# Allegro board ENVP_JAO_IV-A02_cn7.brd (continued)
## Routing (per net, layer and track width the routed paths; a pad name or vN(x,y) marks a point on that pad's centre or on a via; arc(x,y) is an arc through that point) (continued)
GND_+3V3A_L: length 4.9
  TOP w0.254: v1(70.36,85.22) 70.23,85.48 U2.14 69.09,85.48 v1(68.83,85.22)
  TOP w0.508: v1(72.39,80.64) 72.53,80.63 C62.2 ; R47.2 C59.2 72.01,82.3 v1(72.39,82.68)
  vias: v1(67.82,86.23) v1(67.82,85.22) v1(68.33,85.72) v1(68.83,86.23) v1(69.47,80.64) v1(69.47,80.01) v1(70.1,80.64) v1(70.1,80.01) v1(70.36,84.58) v1(70.99,85.22) v1(70.99,84.58)
GND_EARTH: length 71.8
  TOP w0.508: 5,132.07 H2.1 ; H2.1 2.07,135 ; H2.1 5,137.93 ; H2.1 7.93,135
  L2-GND1 w0.508: H2.1 5,137.93 ; H2.1 2.07,135 ; H2.1 5,132.07 ; H2.1 7.93,135 ; CN1.1 6.63,117.98 ; CN1.1 5.54,116.89 ; CN1.1 5.54,119.08
  L6-IN2 w0.508: H2.1 7.93,135 ; H2.1 2.07,135 ; H2.1 5,137.93 ; H2.1 5,132.07 ; 5.54,116.89 CN1.1 ; CN1.1 5.54,119.08 ; CN1.1 6.63,117.98
  L7-GND2 w0.508: CN1.1 6.63,117.98 ; CN1.1 5.54,116.89 ; CN1.1 5.54,119.08 ; H2.1 7.93,135 ; H2.1 2.07,135 ; H2.1 5,137.93 ; H2.1 5,132.07
  BOTTOM w0.508: CN1.1 5.54,119.08 ; CN1.1 6.63,117.98 ; CN1.1 5.54,116.89 ; 2.07,135 H2.1 ; H2.1 5,137.93 ; H2.1 7.93,135 ; H2.1 5,132.07
  vias: v1(1.52,137.41) v1(1.52,135.64) v1(1.52,133.86) v1(1.52,132.33) v1(3.05,138.18) v1(5.46,119.63) v1(6.1,119.63) v1(6.73,119.63) v1(6.86,138.18) v1(7.37,119) v1(7.37,118.36) v1(7.37,117.47) v1(7.37,116.84) v1(7.62,132.33) v1(8.89,138.18) v1(9.14,136.14) v1(9.14,134.37) v1(9.14,132.59) v1(10.16,127.25) v1(10.16,126.49) v1(10.16,125.73) v1(10.16,124.97)
GND_IC:
  vias: v1(11.48,26.42) v1(11.46,25.1) v1(11.84,23.9) v1(13.28,25.27) v1(13.36,26.42) v1(13.36,23.9) v1(15.7,26.39) v1(15.67,25.22) v1(15.7,23.88) v1(18.31,25.15) v1(18.26,23.88) v1(18.36,26.39) v1(19.76,23.88) v1(20.52,25.17) v1(20.57,26.42)
V5V_EN: length 1.4
  TOP w0.102: R549.2 45.26,83.03 U108.4
V5V_OC#: length 2.8
  TOP w0.102: U108.3 47.57,81.71 47.29,81.99 R548.2 TP67.1
V5V_P1: length 18.4
  TOP w0.254: 50.19,78.08 U107.8
  TOP w0.508: R553.1 44.89,70.1 44.57,70.43 44.57,70.85 v1(44.58,70.87) ; 50.19,78.08 50.19,78.38 50.93,79.12 C420.1 50.47,79.81 50.28,79.62 C419.1 49.03,79.62 48.82,79.83 U108.1 47.96,79.17 v1(48.64,78.49)
  BOTTOM w0.508: v1(44.58,70.87) 44.89,70.87 46.25,72.22 46.25,76.12 48.62,78.49 v1(48.64,78.49)
VBUS1_DUT_Q: length 5.2
  BOTTOM w0.508: 27.09,69.02 27.63,69.02 28.19,68.45 28.19,66.04 ; v1(26.67,65.22) 25.23,65.22
  vias: v1(26.67,66.04) v1(26.67,64.14) v1(27.56,65.23) v1(28.19,64.14) v1(28.57,65.23) v1(29.34,65.02) v1(29.34,64.14) v1(29.34,63.25)
VBUS1_EN_R: length 8.2
  TOP w0.508: v1(24,67.12) 24.32,67.12 25.07,66.37 25.07,65.91 24.89,65.74 24,65.74
  BOTTOM w0.508: 27.09,67.12 25.24,67.12 25.23,67.12 v1(24,67.12) 23.88,67.24 TP62.1 24.13,68.45 R529.1
VBUS1_ENABLE_CONSUMER: length 14
  TOP w0.102: v1(31.88,62.74) 32.38,62.74 32.75,62.37 32.75,61.61 33.07,61.29 33.71,61.29 34.05,60.95 34.05,60.14
  L3-IN1 w0.102: v1(26.42,68.07) 27.43,68.07 31.88,63.63 v1(31.88,62.74)
  BOTTOM w0.102: 31.88,63.5 v1(31.88,62.74) ; v1(26.42,68.07) 26.04,68.45 R529.2
VBUS_C_CTRL_OR: length 7.9
  TOP w0.102: TP58.1 59.18,82.93 58.94,83.17 U104.1 58.94,83.81 58.55,84.2 57.02,84.2 56.64,83.82 56.64,82.8 56.26,82.42 55.75,82.42 55.18,81.85 U103.4
VBUS_C_CTRL_P1: length 27.7
  TOP w0.102: U107.12 47.65,76.05 v1(47.5,76.2) ; U100.2 55.37,84.71 54.99,84.33 v1(54.1,84.33) 54.1,82.93 53.9,82.73 R522.1 ; v1(49.02,84.33) 49.13,84.44 U102.1
  L3-IN1 w0.102: v1(54.1,84.33) 53.59,84.84 49.53,84.84 v1(49.02,84.33)
  BOTTOM w0.102: v1(54.1,84.33) 54.1,84.02 R521.2 54.94,83.19 55.5,83.19 56.01,82.68 56.01,79.06 54.16,77.22 48.51,77.22 v1(47.5,76.2)
VBUS_C_CTRL_P1_R: length 47.1
  TOP w0.102: v1(55.24,82.68) 55.37,82.8 U103.2 55.37,84.2 55.63,84.45 56.39,84.45 56.64,84.71 56.64,86.23 56.02,86.85 U100.4 ; v1(33.4,60.83) 33.4,60.14
  BOTTOM w0.102: v1(33.4,60.83) 33.4,59.84 33.6,59.64 34.34,59.64 34.52,59.82 35.48,59.82 36.04,60.38 36.63,60.38 39.17,62.92 39.17,68.63 41.3,70.76 42.14,70.76 45.09,73.71 45.09,75.56 48.52,78.99 51.05,78.99 52.2,77.85 54.36,77.85 55.5,78.99 TP55.1 55.5,82.42 v1(55.24,82.68)
VBUS_C_CTRL_P2: length 36
  TOP w0.102: v1(55.37,76.33) 55.37,76.07 54.84,75.54 U107.38 ; R546.2 R524.1 v1(50.42,84.33) 50.43,84.34 U102.3 ; U101.2 58.17,86.11 v1(57.78,86.49)
  BOTTOM w0.102: v1(55.37,76.33) 56.95,77.9 56.95,79.93 57.63,80.62 57.63,81.81 56.9,82.55 56.9,83.82 57.78,84.71 v1(57.78,86.49) 57.15,87.12 53.72,87.12 52.91,87.93 48.69,87.93 46.86,86.11 46.86,84.2 47.42,83.64 R524.1 v1(50.42,84.33)
VBUS_C_CTRL_P2_R: length 9.2
  TOP w0.102: R547.2 TP56.1 59.69,87.88 58.93,87.88 58.82,87.77 U101.4 58.82,87.11 59.31,86.61 59.31,84.71 59.05,84.45 56.72,84.45 U103.1
VBUS_DISCHARGE_P1: length 9.6
  TOP w0.102: U107.20 48.11,72.05 48.07,72.01 48.07,70.8 45.96,68.69 41.62,68.69 41.1,69.22
VBUS_MON_P1: length 7
  TOP w0.102: R555.2 R556.1 43.94,74.04 44.45,74.55 45.56,74.55 45.92,74.91 45.92,74.93 C425.1 47.62,75.18 47.99,75.54 U107.13
VBUS_P_CTRL_P1: length 23.9
  TOP w0.102: v1(43.94,75.18) 43.94,75.44 44.3,75.79 46.46,75.79 47.31,76.64 48.07,76.64 48.17,76.54 U107.11
  BOTTOM w0.102: v1(43.94,75.18) 43.87,75.11 43.87,72.82 42.04,70.99 41.08,70.99 39.12,69.02 37.91,69.02 37.59,68.71 37.59,62.15 36.4,60.96
VCC_DCIN: length 26.6
  TOP w0.254: C498.1 45.72,123.85 45.47,123.59 v1(45.47,123.19) ; 46.1,121.28 46.1,114.62 43.24,111.76 41.27,111.76 39.12,109.6 39.12,108.71 38.35,107.95 38.35,106.48 37.8,105.92 R696.2 R694.1
  TOP w0.508: 45.34,115.19 44.83,114.68 R845.1
  vias: v1(41.53,110.36) v1(41.53,109.73) v1(42.16,110.36) v1(42.16,109.73) v1(42.8,110.36) v1(42.8,109.73) v1(45.47,125.22) v1(45.47,124.59) v1(45.47,122.17) v1(46.74,125.22) v1(46.74,124.59) v1(46.74,123.19) v1(46.74,122.17) v1(50.04,137.67) v1(50.04,125.48) v1(50.04,124.21) v1(50.29,121.16) v1(50.29,120.4) v1(51.05,125.48) v1(51.05,124.21) v1(51.31,137.67) v1(51.56,121.16) v1(51.56,120.4) v1(52.07,125.48) v1(52.07,124.21) v1(52.83,137.67) v1(52.83,121.16) v1(52.83,120.4) v1(53.34,125.48) v1(53.34,124.21) v1(54.1,121.16) v1(54.1,120.4) v1(54.36,137.67) v1(54.36,125.48) v1(54.36,124.21) v1(55.37,125.48) v1(55.37,124.21) v1(55.37,123.19) v1(55.37,122.17) v1(55.37,121.16) v1(55.37,120.4) v1(56.13,137.67) v1(57.66,137.67)
VCC_DCIN+: length 30.8
  TOP w0.508: CN1.2 5.54,115.27 ; CN1.2 6.63,114.17 ; CN1.2 5.54,113.08 ; R803.1 37.8,107.62 v1(37.72,107.7) ; D31.2 v1(26.86,102.69) ; R700.1 v1(26.04,106.93) ; R425.2 v1(28.19,100.71)
  L2-GND1 w0.508: CN1.2 6.63,114.17 ; CN1.2 5.54,115.27 ; CN1.2 5.54,113.08
  L3-IN1 w0.508: 5.54,113.08 CN1.2 ; CN1.2 5.54,115.27 ; CN1.2 6.63,114.17
  L4-VCC1 w0.508: CN1.2 6.63,114.17 ; CN1.2 5.54,115.27 ; CN1.2 5.54,113.08
  L5-VCC2 w0.508: CN1.2 6.63,114.17 ; CN1.2 5.54,115.27 ; CN1.2 5.54,113.08
  L6-IN2 w0.508: 5.54,113.08 CN1.2 ; CN1.2 5.54,115.27 ; CN1.2 6.63,114.17
  L7-GND2 w0.508: 5.54,113.08 CN1.2 ; CN1.2 6.63,114.17 ; CN1.2 5.54,115.27
  BOTTOM w0.508: 5.54,113.08 CN1.2 ; CN1.2 6.63,114.17 ; CN1.2 5.54,115.27 ; v1(22.1,101.98) 21.51,101.98 R801.1 ; R112.1 v1(20.19,108.2)
  vias: v1(7.37,115.06) v1(7.37,113.28) v1(8.76,114.17) v1(9.4,112.27) v1(9.4,111.25) v1(9.4,110.24) v1(10.67,115.82) v1(10.67,114.55) v1(10.67,113.03) v1(10.92,127.51) v1(10.92,109.35) v1(10.92,108.71) v1(11.56,127.51) v1(12.19,113.03) v1(12.19,109.35) v1(12.19,108.71) v1(12.57,127.51) v1(13.08,117.86) v1(13.08,116.84) v1(13.21,127.51) v1(13.72,113.03) v1(13.72,109.35) v1(13.72,108.71) v1(14.35,127.51) v1(14.99,127.51) v1(15.24,117.86) v1(15.24,116.84) v1(15.24,115.57) v1(15.24,114.3) v1(15.24,113.03) v1(15.24,111.12) v1(15.24,109.86) v1(15.24,108.71) v1(16.13,127.51) v1(16.26,114.94) v1(16.26,114.17) v1(16.26,113.28) v1(16.26,111.89) v1(16.26,111) v1(16.26,110.11) v1(16.76,127.51) v1(16.89,116.59) v1(16.89,115.95) v1(16.89,109.47) v1(17.53,116.59) v1(17.53,115.95) v1(17.53,109.47) v1(17.65,127.51) v1(18.29,127.51) v1(19.81,137.79) v1(19.81,137.03) v1(19.81,135.76) v1(19.81,135.13) v1(19.81,133.99) v1(19.81,133.35) v1(19.81,132.21) v1(19.81,131.57) v1(19.81,130.3) v1(19.81,129.67) v1(19.81,128.52) v1(19.81,127.89)
VCC_DCIN-: length 35
  TOP w0.508: CN1.3 6.63,110.36 ; CN1.3 5.54,109.27 ; CN1.3 5.54,111.46 ; CN1.3 4.45,110.36
  L2-GND1 w0.508: CN1.3 6.63,110.36 ; CN1.3 4.45,110.36 ; CN1.3 5.54,111.46 ; CN1.3 5.54,109.27
  L3-IN1 w0.508: CN1.3 5.54,111.46 ; CN1.3 6.63,110.36 ; CN1.3 5.54,109.27 ; CN1.3 4.45,110.36
  L4-VCC1 w0.508: CN1.3 5.54,111.46 ; CN1.3 4.45,110.36 ; CN1.3 5.54,109.27 ; CN1.3 6.63,110.36
  L5-VCC2 w0.508: 5.54,109.27 CN1.3 ; CN1.3 6.63,110.36 ; CN1.3 5.54,111.46 ; CN1.3 4.45,110.36
  L6-IN2 w0.508: CN1.3 5.54,111.46 ; CN1.3 6.63,110.36 ; CN1.3 5.54,109.27 ; CN1.3 4.45,110.36
  L7-GND2 w0.508: 4.45,110.36 CN1.3 ; CN1.3 5.54,109.27 ; CN1.3 6.63,110.36 ; CN1.3 5.54,111.46
  BOTTOM w0.508: CN1.3 6.63,110.36 ; CN1.3 5.54,109.27 ; CN1.3 5.54,111.46 ; CN1.3 4.45,110.36
  vias: v1(2.54,129.54) v1(2.54,127) v1(2.54,124.46) v1(2.54,121.92) v1(2.54,119.38) v1(2.54,116.84) v1(2.54,114.3) v1(2.54,111.76) v1(2.54,109.22) v1(2.54,106.68) v1(2.54,104.14) v1(2.54,102.23) v1(4.19,110.36) v1(5.08,121.92) v1(5.08,106.68) v1(5.08,104.14) v1(5.08,102.23) v1(5.59,126.49) v1(5.59,125.22) v1(5.59,123.95) v1(5.84,108.71) v1(6.1,129.79) v1(6.1,129.03) v1(6.86,129.79) v1(6.86,129.03) v1(7.49,110.36) v1(7.62,121.92) v1(7.62,106.68) v1(7.62,104.14) v1(7.62,102.23) v1(8.38,126.49) v1(8.38,125.22) v1(8.38,123.95) v1(10.16,102.23) v1(10.67,104.65) v1(10.67,103.63) v1(11.43,105.66) v1(11.43,102.87) v1(12.7,102.23) v1(12.95,105.66) v1(12.95,102.87) v1(14.22,105.66) v1(14.22,102.87) v1(14.73,102.23) v1(14.99,104.65) v1(14.99,103.63) v1(15.62,102.87) v1(16,105.16) v1(16,104.39) v1(16,103.63) v1(16.38,102.23) v1(16.76,105.92) v1(17.14,102.23) v1(17.53,105.92) v1(17.91,102.23) v1(18.29,105.92)
VCC_DCIN_EN: length 6.4
  BOTTOM w0.254: Q66.1 47.48,120.13 47.8,120.45 R702.1 C504.2 R703.1 45.59,119.05 Q67.3
VCC_DCIN_EN_MID: length 1.6
  BOTTOM w0.254: R699.2 47.55,116.73 Q66.3
VCC_DCIN_EN_N: length 17.6
  TOP w0.508: v1(49.02,114.3) 48.1,114.3 47.89,114.08 C622.2
  L3-IN1 w0.508: v1(54.36,114.55) 53.34,115.57 49.78,115.57 49.02,114.81 v1(49.02,114.3)
  BOTTOM w0.508: C502.2 48.79,114.07 v1(49.02,114.3) ; C502.2 47.88,114.94 48.46,115.52 R699.1 49.91,115.95 50.42,116.46 Q62.4 ; C502.2 46.43,114.07 R695.2 ; Q63.4 54.1,114.3 v1(54.36,114.55)
VCC_DCIN_PG: length 3
  TOP w0.203: U124.14 35.21,107.6 35.43,107.82 TP101.1 36.7,107.11 R803.2
VCC_DCIN_Q:
  vias: v1(46.1,112.39) v1(46.1,111.76) v1(46.74,112.39) v1(49.02,113.16) v1(49.02,112.39) v1(49.02,111.76) v1(49.66,113.79) v1(49.66,113.16) v1(49.66,112.39) v1(49.66,111.76) v1(50.04,114.43) v1(50.67,114.43) v1(50.8,111.76) v1(51.44,111.76) v1(51.56,114.43) v1(52.32,111.76) v1(52.45,114.43) v1(52.96,111.76) v1(53.09,114.43)
VCC_SRC: length 47.8
  TOP w0.508: C44.1 75.34,94.11 ; C44.1 74.45,93.22 ; C44.1 76.23,93.22 ; C44.1 75.34,92.33 ; C45.1 75.34,102.62 ; C45.1 75.34,100.84 ; C45.1 76.23,101.73 ; C45.1 74.45,101.73 ; R115.1 84.38,92.2 v1(83.82,92.2) ; v1(73.79,104.44) R477.1 72.47,104.44 72.39,104.52 D1.2 ; R32.1 v1(68.58,80.64) ; v1(73.91,88.9) 74.17,88.65 R30.1
  L4-VCC1 w0.508: 74.45,101.73 C45.1 ; C45.1 75.34,102.62 ; C45.1 76.23,101.73 ; C45.1 75.34,100.84 ; 74.45,93.22 C44.1 ; C44.1 75.34,94.11 ; C44.1 76.23,93.22 ; C44.1 75.34,92.33
  L6-IN2 w0.508: C44.1 75.34,90.32 v1(73.91,88.9)
  BOTTOM w0.508: 75.34,100.84 C45.1 ; C45.1 76.23,101.73 ; C45.1 75.34,102.62 ; C45.1 74.45,101.73 ; C44.1 75.34,94.11 ; C44.1 74.45,93.22 ; C44.1 75.34,92.33 ; C44.1 76.23,93.22 ; v1(73.91,88.9) 73.91,79.25 73.15,78.49 69.09,78.49 68.58,78.99 v1(68.58,80.64)
  vias: v1(59.05,115.19) v1(59.05,114.55) v1(59.94,115.19) v1(59.94,114.55) v1(60.83,115.19) v1(60.83,114.55) v1(61.98,126.11) v1(61.98,125.48) v1(61.98,124.84) v1(61.98,124.21) v1(61.98,121.92) v1(61.98,121.28) v1(62.61,121.92) v1(62.61,121.28) v1(62.61,117.98) v1(62.61,117.35) v1(62.87,115.32) v1(63.25,117.98) v1(63.25,117.35) v1(63.5,115.32) v1(63.63,121.92) v1(63.63,121.28) v1(63.88,117.98) v1(63.88,117.35) v1(64.26,121.92) v1(64.26,121.28) v1(65.02,115.32) v1(65.66,115.32) v1(67.18,117.98) v1(67.18,117.35) v1(67.44,115.32) v1(67.82,117.98) v1(67.82,117.35) v1(67.82,95) v1(68.07,115.32) v1(68.45,101.98) v1(68.45,101.09) v1(68.45,95) v1(69.34,102.87) v1(69.34,101.98) v1(69.34,101.09) v1(69.34,95) v1(69.98,95) v1(70.36,101.98) v1(70.36,101.09) v1(70.87,95) v1(71.12,102.87) v1(71.5,95) v1(71.63,101.98) v1(71.63,101.09) v1(72.39,95) v1(72.39,94.36) v1(72.9,102.87) v1(73.15,101.09) v1(73.15,100.08) v1(73.15,99.06) v1(73.15,98.04) v1(73.15,97.03) v1(73.15,96.01) v1(73.79,94.74) v1(73.91,101.47) v1(73.91,93.22) v1(74.36,102.87) v1(74.68,97.54) v1(74.68,95.5) v1(75.31,100.08) v1(75.31,98.81) v1(75.31,94.61) v1(75.82,86.11) v1(75.82,85.47) v1(75.82,84.84) v1(75.82,82.8) v1(76.2,97.54) v1(76.2,95.5) v1(76.45,86.11) v1(76.45,85.47) v1(76.45,84.84) v1(76.45,82.8) v1(76.58,100.08) v1(76.58,98.81) v1(76.71,101.47) v1(76.71,93.22) v1(77.09,86.11) v1(77.09,85.47) v1(77.09,84.84) v1(77.09,82.8) v1(77.47,84.07) v1(77.47,83.44) v1(77.72,86.11) v1(77.72,85.47) v1(77.72,84.84) v1(78.11,84.07) v1(78.11,83.44) v1(83.19,92.84) v1(83.19,92.2) v1(83.82,92.84) v1(86.11,92.71) v1(86.11,92.08) v1(86.74,92.96) v1(86.74,92.33) v1(151.51,101.09) v1(151.51,95.12) v1(151.76,104.78) v1(152.15,92.13) v1(152.4,101.09) v1(152.4,95.12) v1(152.63,99.59) v1(152.65,103.63) v1(152.9,97.79) v1(153.29,101.09) v1(153.31,95.12) v1(153.42,103.63) v1(153.54,99.57) v1(153.55,97.53) v1(153.61,98.17) v1(153.8,93.85) v1(154.69,104.78) v1(154.69,104.14) v1(155.32,104.78) v1(155.32,104.14) v1(155.96,104.78) v1(155.96,104.14)
VCC_SRC_FET: length 51.8
  TOP w0.381: C380.1 R705.1 90.55,87.76 v1(89.92,87.12)
  BOTTOM w0.381: 59.05,106.17 61.59,106.17 62.48,105.28 66.29,105.28 67.82,103.76 80.01,103.76 80.53,103.24 80.53,88.63 81.14,88.02 89.01,88.02 v1(89.92,87.12)
  BOTTOM w0.508: 56.9,104.27 57.53,103.63 C126.1
  vias: v1(21.34,56.64) v1(21.34,56.01) v1(21.34,54.74) v1(21.34,54.1) v1(21.97,56.64) v1(21.97,56.01) v1(21.97,54.74) v1(21.97,54.1) v1(23.75,56.64) v1(23.75,56.01) v1(23.75,54.74) v1(23.75,54.1) v1(24.38,56.64) v1(24.38,56.01) v1(24.38,54.74) v1(24.38,54.1) v1(26.04,59.44) v1(26.04,58.8) v1(26.29,56.64) v1(26.29,56.01) v1(26.29,54.74) v1(26.29,54.1) v1(26.67,59.44) v1(26.67,58.8) v1(26.92,56.64) v1(26.92,56.01) v1(26.92,54.74) v1(26.92,54.1) v1(28.19,59.44) v1(28.19,58.8) v1(28.83,59.44) v1(28.83,58.8) v1(31.11,58.67) v1(31.11,58.04) v1(31.11,56.52) v1(31.11,55.88) v1(31.11,54.61) v1(31.11,53.98) v1(31.75,58.67) v1(31.75,58.04) v1(31.75,56.52) v1(31.75,55.88) v1(31.75,54.61) v1(31.75,53.98) v1(32.77,58.67) v1(32.77,58.04) v1(32.77,56.52) v1(32.77,55.88) v1(32.77,54.61) v1(32.77,53.98) v1(33.91,58.67) v1(33.91,58.04) v1(34.54,58.67) v1(34.54,58.04) v1(35.18,58.67) v1(35.18,58.04) v1(36.32,58.67) v1(36.32,58.04) v1(36.32,57.4) v1(36.96,58.67) v1(36.96,58.04) v1(36.96,57.4) v1(52.07,106.17) v1(52.07,105.54) v1(53.09,106.17) v1(53.09,105.54) v1(53.09,104.52) v1(53.09,103.89) v1(54.1,106.17) v1(54.1,105.54) v1(54.1,104.52) v1(54.1,103.89) v1(54.86,106.17) v1(54.86,105.54) v1(55.63,106.17) v1(55.63,105.54) v1(56.39,106.17) v1(56.39,105.54) v1(57.4,106.17) v1(57.4,105.54) v1(58.17,105.54)
VCCD_1V8: length 2.4
  TOP w0.254: C418.2 56.77,73.05 U107.33
VDD1: length 2.7
  BOTTOM w0.254: 28.92,95.96 28.92,96.84 29.87,97.79 C457.1
VDD12V_DISCHARGE: length 63.9
  TOP w0.102: Q16.1 78.67,136.84 80.64,138.81 86.87,138.81 v1(87.86,137.82)
  BOTTOM w0.102: v1(87.86,137.82) 87.86,131.22 88.39,130.68 88.39,125.86 87.95,125.41 87.95,116.78 85.72,114.55 84.45,114.55 77.6,107.7 73.03,107.7 71.37,109.35 71.37,110.11 70.99,110.49 69.72,110.49 69.34,110.11 69.34,109.73 68.83,109.22 67.06,109.22 66.67,108.84 66.67,108.13 R109.2 67.71,107.1 D4.3
VDD_1V2:
  vias: v1(136.06,30.08) v1(138.22,36.77) v1(139.19,36.77) v1(140.91,36.64) v1(145.67,34.16) v1(145.92,32.38)
VDD_1V8: length 29.2
  TOP w0.254: 70.87,110.67 Q14.2
  TOP w0.305: 15.11,50.89 15.11,50.5 15.75,49.86
  TOP w0.381: 15.06,54.1 v1(16.13,54.1) ; v1(14.99,49.4) 14.53,48.95 14.35,48.95 ; v1(16.38,49.86) 15.75,49.86
  TOP w0.508: 70.87,110.67 70.74,110.54 v1(70.74,109.98) 70.74,109.27 R105.1
  BOTTOM w0.254: 37.97,84.71 37.97,84.33 37.63,83.99 37.01,83.99 ; 37.26,79.5 37.26,78.82 37.72,78.36 37.72,77.34 37.5,77.13 37.01,77.13
  BOTTOM w0.381: 41.61,84.84 v1(42.42,84.84) ; 41.61,82.55 v1(42.42,82.55) ; 41.61,78.61 v1(42.29,78.61) ; 41.61,81.41 42.16,81.41 v1(42.29,81.28) ; 41.61,77.34 42.04,77.34 v1(42.29,77.6) ; 41.61,83.69 v1(42.42,83.69) ; 41.61,75.95 41.61,74.37 41,73.76 v1(41,73.41)
  BOTTOM w0.508: 96.44,78.87 95.49,77.91 95.49,76.82 95.15,76.48 v1(95.15,76.45) ; 37.26,79.5 36.14,79.5 v1(36.14,78.74) ; 37.97,84.71 37.97,85.52 37.59,85.9 37.08,85.39 v1(37.08,85.22) ; 36.32,86.82 36.5,86.82 v1(36.96,86.36) ; 184.48,29.72 v1(184.48,33.02)
  vias: v1(26.54,44.4) v1(29.34,44.7) v1(30.61,29.97) v1(32.89,29.97) v1(37.34,29.97) v1(41.88,69.47) v1(42.57,69.47) v1(56.64,28.83) v1(64.52,79.76) v1(65.15,79.76) v1(65.15,79.12) v1(65.79,79.76) v1(65.79,79.12) v1(65.79,78.49) v1(88.2,73.24) v1(88.33,73.88) v1(88.86,73.24) v1(88.99,73.88) v1(95.89,81.79) v1(97.54,77.09) v1(107.06,78.49) v1(108.2,80.77) v1(110.36,84.26) v1(112.46,84.26) v1(113.16,46.74) v1(113.79,84.07) v1(114.53,46.71) v1(115.32,51.82) v1(119.89,79.76) v1(120.52,88.28) v1(120.5,87.6) v1(121.15,87.59) v1(121.17,88.27) v1(126.36,77.72) v1(137.97,70.43) v1(138.05,62.1) v1(138.18,63.75) v1(139.57,72.97) v1(140.49,58.75) v1(140.77,76.12) v1(142.21,77.57) v1(143.64,74.68) v1(150.81,63.06) v1(153.54,54.61) v1(154.81,56.52) v1(157.23,64.01) v1(163.58,45.59) v1(164.97,53.92) v1(165.23,49.53) v1(169.54,74.04) v1(171.2,61.72) v1(171.3,31.75) v1(172.47,31.75) v1(173.61,62.48) v1(173.61,61.21) v1(173.61,59.94) v1(173.61,57.4) v1(173.74,56.13) v1(175.84,51.61) v1(175.97,49.83) v1(176.73,38.18) v1(177.42,102.49) v1(177.62,28.52) v4(163.64,94.55)
VDD_1V8_PG: length 1.6
  TOP w0.102: v1(81.28,80.77) 81.14,80.91 U3.5
  BOTTOM w0.102: v1(81.28,80.77) 81.36,80.85 R72.2
VDD_3V3: length 109
  TOP w0.254: 92.22,114.74 92.22,113.3 91.95,113.03 v1(91.57,113.03) 91.57,113.41 91.72,113.56 91.72,114.74
  TOP w0.508: v1(17.14,58.93) 17.73,58.93 18.8,60.12 ; v1(85.6,64.39) 86.36,63.63 86.36,62.23 87.76,60.83 v1(87.76,60.2) 87.76,60.07 86.79,59.11 83.74,59.11 80.26,55.63 v1(80.26,53.98) ; 18.8,64.34 v1(18.8,65.02) ; v1(42.93,77.6) 42.93,77.19 42.19,76.45 41.53,76.45 40.77,75.69 34.92,75.69 v1(33.53,74.3) ; R550.1 v1(44.58,73.91) ; v1(91.57,113.03) v1(90.93,113.03)
  L3-IN1 w0.508: v1(14.22,64.39) 14.86,65.02 v1(18.8,65.02) 24.38,70.61 v1(26.04,70.61) 28.45,73.03 v1(30.86,73.03) 32.26,73.03 v1(33.53,74.3) ; v1(180.8,41.27) 180.8,35.61 183.9,32.51 183.9,24.64 v1(184.28,24.26)
  L6-IN2 w0.508: v1(35.78,88.32) 33.57,86.11 v1(31.88,86.11) 31.11,86.87 27.94,86.87 27.18,86.11 v1(26.04,86.11)
  BOTTOM w0.381: 32.72,74.3 v1(33.53,74.3) ; v1(87.76,60.2) 88.21,59.74 88.39,59.74 ; 30.86,72.34 v1(30.86,73.03) ; v1(88.77,105.79) 88.52,105.79 88.34,105.97 R649.1 ; 183.59,24.26 v1(184.28,24.26) ; v1(85.6,64.39) R502.1
  BOTTOM w0.508: v1(26.04,70.61) 26.04,70.99 26.16,71.12 R674.2 R671.2 ; v1(14.22,64.39) 13.84,64.01 13.84,59.44 14.35,58.93 v1(17.14,58.93) ; R617.2 R620.2 v1(26.04,86.11) ; R73.1 78.54,82.09 v1(78.74,82.3) ; 30.73,86.79 31.88,86.79 v1(31.88,86.11) ; 90.63,113.97 C467.1
  vias: v1(35.76,89.62) v1(35.78,88.95) v1(36.4,89.62) v1(36.41,88.95) v1(36.41,88.32) v1(37.29,89.6) v1(37.29,88.94) v1(37.29,88.3) v1(37.92,89.6) v1(37.92,88.94) v1(37.92,88.3) v1(38.73,91.88) v1(38.73,91.25) v1(38.73,90.36) v1(38.73,89.73) v1(38.73,89.03) v1(38.73,88.39) v1(39.37,91.88) v1(39.37,91.25) v1(39.37,90.36) v1(39.37,89.73) v1(39.37,89.03) v1(39.37,88.39) v1(51.56,37.97) v1(52.2,37.97) v1(52.83,37.97) v1(60.58,35.43) v1(60.71,36.58) v1(61.59,30.61) v1(73.66,32.51) v1(74.3,32.51) v1(77.47,30.61) v1(93.47,110.49) v1(94.11,110.49) v1(94.22,113.05) v1(119.91,78.51) v1(123.06,88.3) v1(123.57,88.86) v1(123.7,88.23) v1(124.21,88.77) v1(127.51,77.34) v1(127.89,80.26) v1(132.33,75.31) v1(136.78,69.53) v1(138.75,82.61) v1(139.32,77.98) v1(141.1,138.05) v1(142.49,59.37) v1(142.81,56.89) v1(142.88,55.72) v1(143.13,64.45) v1(143.45,73.72) v1(144.36,68.16) v1(148.97,81.53) v1(149.61,81.53) v1(149.61,80.9) v1(151.13,81.53) v1(151.13,80.9) v1(152.78,81.53) v1(152.78,80.9) v1(153.37,113.79) v1(153.42,80.9) v1(154.05,117.09) v1(155.83,93.41) v1(156.21,115.06) v1(156.95,90.65) v1(157.23,112.39) v1(157.23,111.76) v1(157.35,64.64) v1(157.86,112.39) v1(157.86,111.76) v1(158.5,112.83) v1(158.5,112.19) v1(158.5,111.56) v1(159.13,112.83) v1(159.13,112.19) v1(159.13,111.56) v1(160.78,136.02) v1(160.91,33.91) v1(165.23,48.26) v1(166.31,108.08) v1(167.26,112.01) v1(167.26,51.18) v1(167.39,122.17) v1(168.91,104.39) v1(175.9,85.34) v1(175.9,84.71) v1(175.9,84.07) v1(176.53,85.34) v1(176.53,84.71) v1(176.53,84.07) v1(177.29,119.34) v1(177.29,118.71) v1(177.29,118.07) v1(177.93,119.34) v1(177.93,118.71) v1(177.93,118.07) v4(132.2,102.01) v4(132.81,102.01) v4(164.2,106.24) v4(164.2,105.63)
VDD_3V3_EN: length 2.3
  TOP w0.102: U2.10 68.08,83.01 R106.1
VDD_3V3_PD: length 69.1
  TOP w0.254: C400.1 57.84,88.44 57.52,88.12 U101.5 ; C397.1 51.93,88.58 U98.5 ; U102.5 49.78,88.01 49.61,88.19 C401.1 ; C399.1 54.91,88.32 54.72,88.12 U100.5 ; U107.31 54.6,71.88 ; U107.32 55.6,72.54 55.75,72.39
  TOP w0.381: v1(60.33,80.01) 60.33,80.44 R526.1 ; v1(56.64,81.41) 56.01,80.77 C402.1 55.83,81.66 U103.5 ; U104.5 58.29,80.77 58.88,80.19 C403.1 v1(59.69,80.01)
  TOP w0.508: R552.1 45,77.47 44.58,77.89 v1(44.58,78.49) ; v1(49.02,82.04) 49.02,82.42 49.28,82.68 R546.1 ; C397.1 v1(50.93,88.77) ; R850.2 61.29,71.25 v1(60.58,71.96) ; v1(50.93,69.85) 50.22,69.14 R782.1 ; C401.1 v1(50.29,88.77) ; R525.1 v1(47.5,84.33) ; R557.1 53.21,80.85 v1(53.21,81.41) ; v1(52.96,70.36) 52.96,69.16 R559.1 R558.1 ; C399.1 v1(54.23,88.77) ; R708.2 45.29,112.7 v1(45.21,112.78) ; C400.1 v1(57.15,88.77) ; R547.1 v1(59.94,84.96) ; 55.75,72.39 56.18,71.96 C416.1 v1(57.53,71.96) ; 54.6,71.88 54.74,71.88 56.69,69.93 C414.1 57.09,69.93 v1(57.53,69.48) ; R339.1 v1(52.32,82.04) ; v1(38.86,60.58) 38.9,60.62 39.81,60.62 39.81,61.53 39.62,61.72 37.85,61.72 37.47,62.1 36.4,62.1 36.4,60.96
  L6-IN2 w0.508: v1(45.21,112.78) 43.69,111.25 43.69,107.95
  BOTTOM w0.305: v1(49.66,86.23) 49.23,86.23 C398.1 48.99,85.56 U99.5 ; C396.1 52.32,84.71 52.2,84.83 U97.5
  BOTTOM w0.508: 36.4,59.82 38.1,59.82 v1(38.86,60.58) 39.6,61.32 39.6,68.43 41.34,70.17 45.21,70.17 v1(45.72,70.68) ; v1(51.56,84.33) 51.56,84.15 52.07,83.64 C396.1 ; R704.1 v1(45.21,112.78)
  vias: v1(48.01,105.54) v1(48.01,103.76) v1(48.64,105.54) v1(48.64,103.76) v1(49.28,105.54) v1(49.28,103.76)
VDD_3V3_PD_PG: length 3.2
  TOP w0.254: U127.7 44.84,109.72 44.07,110.49 TP92.1 43.94,111.12 44.37,111.56 R708.1
VDD_3V3_PD_PGADJ: length 2.4
  TOP w0.102: R706.2 48.91,109.03 v1(48.64,109.03) 48.33,108.72 U127.2
  BOTTOM w0.102: R707.2 v1(48.64,109.03)
VDD_3V3_PG: length 106.7
  TOP w0.102: 90.25,55.12 90.25,61.65 86.87,65.02 86.87,70.89 87.88,71.91 92.86,71.91 94.5,73.55 94.5,78.19 93.04,79.65 93.04,82.22 91.25,84.01 91.25,85.03 v1(89.92,86.36) ; R53.1 v1(76.58,88.65) ; U2.1 69.08,87.36 70.51,88.8 70.51,89.51 R38.2 v1(71.12,90.81) ; U107.4 52.19,77.84 52.7,78.36 55.01,78.36 55.62,78.97 60.6,78.97 v1(61.98,77.6)
  BOTTOM w0.102: 74.93,88.65 v1(76.58,88.65) 77.09,89.15 79.49,89.15 80.99,87.66 88.62,87.66 v1(89.92,86.36) ; 74.93,88.65 73.91,89.66 71.63,89.66 71.12,90.17 v1(71.12,90.81) ; 74.93,88.65 74.37,88.09 74.37,78.74 73.61,77.98 68.65,77.98 67.94,78.68 67.94,80.39 66.8,81.53 64.01,81.53 61.98,79.5 v1(61.98,77.6)
VDD_5V: length 29.2
  TOP w0.508: v1(84.07,102.74) 82.02,102.74 80.27,104.5 v1(74.68,104.5) ; 187.32,29.01 v1(187.32,27.43) ; v1(67.18,108.58) 67.69,108.08 R95.1 ; v1(67.18,108.58) 66.62,108.03 R96.1 ; v1(67.18,108.58) 67.74,109.14 R107.1 ; v1(8.12,36.32) 8.12,35.62 6.93,35.62 6.93,34.16
  BOTTOM w0.254: 35.38,77.13 35.17,77.13 34.98,77.32 34.98,77.72 v1(35.1,77.85) ; 35.38,83.99 35.01,83.99 34.8,84.2 34.8,84.45 v1(35.05,84.71)
  BOTTOM w0.508: v1(67.18,108.58) 67.69,108.08 R95.1 70.41,108.03 72.26,106.17 73,106.17 v1(74.68,104.5)
  vias: v1(22.35,49.15) v1(22.99,49.15) v1(36.45,67.42) v1(37.08,67.42) v1(37.21,80.9) v1(37.21,80.26) v1(37.16,68.07) v1(37.97,80.9) v1(37.97,80.26) v1(38.1,68.07) v1(38.73,68.07) v1(40.39,68.2) v1(40.44,67.55) v1(40.44,66.9) v1(41.78,60.71) v1(41.78,60.07) v1(41.91,62.74) v1(41.91,62.1) v1(41.91,58.67) v1(41.91,58.04) v1(42.42,60.71) v1(42.42,60.07) v1(42.55,62.74) v1(42.55,62.1) v1(42.55,58.67) v1(42.55,58.04) v1(43.18,62.74) v1(43.18,62.1) v1(43.43,58.67) v1(43.43,58.04) v1(43.81,62.74) v1(43.81,62.1) v1(44.07,58.67) v1(44.07,58.04) v1(44.22,30.25) v1(44.7,58.67) v1(44.7,58.04) v1(44.86,30.23) v1(44.96,62.74) v1(44.96,62.1) v1(44.96,30.86) v1(45.59,62.74) v1(45.59,62.1) v1(45.59,58.67) v1(45.59,58.04) v1(46.23,62.74) v1(46.23,62.1) v1(46.23,60.71) v1(46.23,60.07) v1(46.23,58.67) v1(46.23,58.04) v1(46.86,62.74) v1(46.86,62.1) v1(46.86,60.71) v1(46.86,60.07) v1(46.86,58.67) v1(46.86,58.04) v1(62.97,27.89) v1(63.37,28.4) v1(63.8,28.88) v1(69.34,28.7) v1(69.34,28.07) v1(69.98,28.7) v1(69.98,28.07) v1(78.87,24.77) v1(78.87,24) v1(78.87,23.37) v1(79.38,24.38) v1(84.07,102.11) v1(84.07,101.09) v1(84.07,100.46) v1(84.71,102.74) v1(84.71,102.11) v1(84.71,101.09) v1(84.71,100.46) v1(85.34,105.54) v1(85.34,104.9) v1(85.98,105.54) v1(85.98,104.9) v1(86.08,56.67) v1(86.23,54.88) v1(86.49,53.34) v1(86.49,52.7) v1(86.61,105.54) v1(86.61,104.9) v1(86.72,56.67) v1(87.35,24.32) v1(87.5,24.96) v1(88.02,25.34) v1(87.96,24.51) v1(88.27,56.79) v1(88.33,54.88) v1(88.9,56.79) v1(94.36,81.92) v1(115.67,108.23) v1(116.08,108.74) v1(116.18,107.85) v1(116.59,108.36) v1(116.71,108.99) v1(117.25,109.35) v1(122.43,106.55) v1(122.91,107.01) v1(128.91,108.2) v1(129.29,108.71) v1(129.67,109.22) v1(130.05,109.73) v1(130.63,110.06) v1(131.06,110.54) v1(168.28,39.12) v1(168.28,38.48) v1(181.86,29.13) v1(182.63,29.13) v1(182.63,28.45)
VDD_12V:
  vias: v1(81.79,135.38) v1(81.79,134.75) v1(82.42,135.38) v1(82.42,134.75) v1(83.19,135.38) v1(83.19,134.75) v1(83.82,135.38) v1(83.82,134.75) v1(173.99,127) v1(173.99,126.36) v1(173.99,125.73) v1(173.99,125.09) v1(174.62,127) v1(174.62,126.36) v1(174.62,125.73) v1(174.62,125.09) v1(175.26,127) v1(175.26,126.36) v1(175.26,125.73) v1(175.26,125.09)
VDD_12V_ENABLE: length 1.2
  TOP w0.102: Q14.3 71.37,110.57 R108.2
VDD_AV1V1_HUB:
  vias: v1(66.27,40.59) v1(66.71,35.75) v1(67.26,35.26) v1(77.93,37.26) v1(78.61,47.68) v1(79.25,47.75) v1(79.91,47.68) v1(81.05,43.48) v1(86.61,38.86) v1(86.61,38.23) v1(87.25,38.86) v1(87.25,38.23) v1(87.88,38.86) v1(87.88,38.23) v1(88.52,38.86) v1(88.52,38.23)
VDD_XFI12_LVS:
  vias: v1(115.19,131.32)
VDDD_IN_CCG4:
  vias: v1(42.04,107.06) v1(42.04,106.43) v1(42.04,105.79) v1(42.04,105.16) v1(42.04,104.52) v1(42.04,103.89) v1(43.81,107.06) v1(43.81,106.43) v1(43.81,105.79) v1(43.81,104.52) v1(43.81,103.89) v1(43.81,103.25)
VIN_PWR_ON: length 93.8
  TOP w0.102: R117.2 68.25,103.5 80.26,103.5 80.64,103.12 80.64,89.79 80.39,89.53 75.31,89.53 74.8,89.03 74.8,76.83 70.49,72.52 67.44,72.52 v1(66.93,72.01) 64.77,69.85 61.85,69.85 59.13,67.13 R23.1
  BOTTOM w0.102: v1(66.93,72.01) 67.56,71.37 83.46,71.37 85.34,69.49 85.34,67.31 85.78,66.87 85.78,65.22 86.03,64.97 86.54,64.97 87.12,64.39 R502.2 87.5,64.39 88.13,65.01 89.45,65.01
VIN_PWR_ON_5V: length 2.7
  TOP w0.254: Q3.1 57.56,66.22 R23.2 R24.1
VIN_PWR_ON_SRC: length 3
  TOP w0.254: Q19.1 64.77,101.78 R118.1 R117.1
VSS1: length 2.2
  BOTTOM w0.254: 25.42,95.96 25.42,97.95 C461.1
VSS2: length 2.4
  BOTTOM w0.254: 25.42,80.46 25.42,81.99 C475.1
AQR113C_TX_N:
  vias: v2(107.24,42.16) v3(107.24,42.16) v4(107.19,42.66) v5(138.17,84.9) v6(138.17,84.9)
AQR113C_TX_P:
  vias: v2(107.75,42.16) v3(107.75,42.16) v4(107.8,42.66) v5(138.68,84.9) v6(138.68,84.9)
BRD_SEL: length 2.3
  BOTTOM w0.102: R501.2 87.2,65.53 89.54,65.53
CAM_2V8_BODE: length 2.3
  TOP w0.254: R655.2 82.22,106.05 C478.1 R656.1
CAM_2V8_BOOT: length 3.1
  TOP w0.254: U117.7 86.75,108.71 86.49,108.97
  TOP w0.508: C471.1 84.63,109.55 85.22,108.97 86.49,108.97
CAM_2V8_EN: length 2.7
  TOP w0.102: R651.2 84.45,105.28 85.09,105.92 85.09,106.3 85.61,106.82 U117.11
CAM_2V8_FB: length 1.7
  TOP w0.254: U117.10 85.48,107.32 85.17,107.01 R657.1
CAM_2V8_FB_R: length 3.4
  TOP w0.254: R656.2 C478.2 83.13,105.92 R658.1 R657.2
CAM_2V8_PG: length 1.9
  TOP w0.254: v1(88.77,108.46) 88.63,108.32 U117.5
  BOTTOM w0.254: v1(88.77,108.46) 88.32,108.92 R653.2
CAM_2V8_SNUB: length 1.8
  TOP w0.508: R654.2 83.81,112 84.33,112.52 C477.1
CAM_AVDD_EN: length 2
  TOP w0.102: v1(83.95,105.54) 83.82,105.41 83.82,104.27 84.02,104.06 R651.1
CAM_SPI_CS0: length 2.6
  TOP w0.102: TP98.1 93.22,122.18 93.22,120.47
CAN0_DIN: length 120.5
  TOP w0.102: v1(90.42,97.79) 91.49,97.79 R759.2 ; v1(18.16,72.14) 18.26,72.03 18.26,70.26 19.94,68.58 19.94,64.44 18.8,63.42 17.65,63.42 17.24,63.01 16.58,63.01
  L6-IN2 w0.089: v1(90.42,97.79) 90.42,97.28 90.86,96.85 90.86,88.47 92.13,87.19 92.13,79.63 91.69,79.19 91.69,76.36 90.01,74.68 87.94,74.68 86.83,73.58 69.81,73.58 67.76,71.53 56.86,71.53 54.74,73.66 54.74,75.81 53.92,76.63 45.78,76.63 45.54,76.39 45.53,76.39 45.21,76.07 36.47,76.07 35.49,77.05 34.71,77.05 34.39,77.37 32.08,77.37 30.96,78.49 24.51,78.49 22.48,76.45 20.57,76.45 18.67,74.55 18.67,72.64 v1(18.16,72.14)
CAN0_DOUT: length 119.1
  TOP w0.102: R758.2 91.82,96.01 91.19,95.38 v1(89.92,95.38) ; v1(18.16,74.55) 18.67,74.04 18.67,70.48 20.45,68.71 20.45,63.63 19.3,62.48 19.3,61.47 19.13,61.29 18.8,61.04 17.65,61.04 17.62,61.06 16.58,61.06
  L6-IN2 w0.089: v1(18.16,74.55) 22.23,78.61 23.11,78.61 23.37,78.87 32.64,78.87 32.94,78.56 35,78.56 36.77,76.79 43.27,76.79 43.83,77.36 54.96,77.36 56.52,75.8 56.52,75.69 57.66,74.55 57.66,73.69 58.45,72.9 67.56,72.9 68.97,74.3 86.53,74.3 87.64,75.41 89.71,75.41 90.97,76.66 90.97,79.49 91.41,79.93 91.41,84.99 90.82,85.57 90.82,87.48 90.13,88.17 90.13,95.16 v1(89.92,95.38)
CAN_BUS_SET: length 128.1
  TOP w0.102: R760.2 v1(91.14,102.11) ; 13.78,61.06 13.69,61.06 12.45,59.82 v1(10.92,59.82)
  L6-IN2 w0.102: v1(91.14,102.11) 90.7,101.68 90.7,99.16 91.22,98.65 91.22,89.44 92.49,88.17 92.49,79.21 92.65,79.05 92.65,78.31 92.11,77.76 92.11,76.26 90.16,74.32 88.09,74.32 86.98,73.22 69.97,73.22 67.93,71.17 56.71,71.17 55.93,71.96 49.35,71.96 49.09,72.22 49.09,74.55 47.93,75.7 36.32,75.7 35.8,76.23 32.99,76.23 32.29,76.93 24.23,76.93 22.73,75.43 22.13,75.43 11.43,64.73 11.43,60.33 v1(10.92,59.82)
CARRIER_POWER_ON: length 109.5
  TOP w0.102: R52.1 v1(77.72,88.65) 78.11,89.03 80.52,89.03 82.56,91.07 Q18.1 ; R106.2 67.44,81.03 v1(67.06,80.64)
  L3-IN1 w0.089: v1(60.07,69.47) 60.83,70.23 84.33,70.23 87.88,66.67 93.47,66.67 v1(94.61,67.82)
  L6-IN2 w0.089: v1(77.72,88.65) 78.11,89.03 82.68,89.03 85.24,91.59 85.24,92.96 87.35,95.07 87.35,95.75 88.05,96.44 88.05,98.41 89.07,99.43 89.07,103.37 89.79,104.09 v1(89.79,104.39)
  BOTTOM w0.102: v1(94.61,67.82) 94.23,68.2 94.23,68.71 94.03,68.91 R497.2 ; v1(60.07,69.47) 63.12,72.52 63.12,80.01 64.21,81.1 66.6,81.1 v1(67.06,80.64) 67.44,80.26 67.44,78.49 68.45,77.47 73.79,77.47 74.8,78.49 74.8,87 75.95,88.14 77.22,88.14 v1(77.72,88.65)
CARRIER_SHUTDOWN_N: length 10.2
  BOTTOM w0.102: R463.2 TP33.1 94.49,74.8 94.49,75.06 94.38,75.17 U77.3 93.23,75.17 93.09,75.31 93.09,78.81 92.65,78.81 92.2,78.36 91,78.36 Q38.3
CCG4_LED: length 112.4
  TOP w0.102: v1(13.59,49.53) 12.57,49.53 12.22,49.88 12.22,50.7 12.24,50.72 12.24,51.31 10.48,51.31 10.16,50.99 ; v1(59.44,69.47) 60.2,70.23 64.52,70.23 67.16,72.87 67.54,72.87 67.82,73.15 67.82,74.55 67.44,74.93 65.41,74.93 61.47,78.87 61.47,81.03 60.33,82.17 57.28,82.17 57.15,82.04 57.15,81.15 56.2,80.2 54.67,80.2 53.66,81.22 53.66,81.72 53.47,81.92 52.96,81.92 52.77,81.72 52.77,79.57 51.19,77.98 U107.6
  L6-IN2 w0.102: v1(59.44,69.47) 59.02,69.05 53.38,69.05 51.92,70.51 48.77,70.51 46.17,73.11 43.24,73.11 42.37,73.98 34.98,73.98 34.16,74.79 32.5,74.79 31.93,74.22 30.43,74.22 29.69,74.95 24.28,74.95 23.33,74 22.72,74 12.95,64.23 12.95,50.16 v1(13.59,49.53)
COM1_SET: length 92
  TOP w0.102: v1(89.41,94.23) 89.79,94.61 R738.2 ; v1(28.7,86.11) 29.15,86.55 29.15,87.01 28.59,87.01 28.44,86.86 27.69,86.86
  L6-IN2 w0.102: v1(28.7,86.11) 34.8,80.01 34.8,79.27 36.92,77.15 43.12,77.15 43.68,77.72 55.11,77.72 55.71,77.12 56.52,77.12 58.97,74.66 86.38,74.66 87.49,75.77 89.56,75.77 90.61,76.81 90.61,79.64 91.05,80.08 91.05,84.79 90.46,85.37 90.46,87.33 89.77,88.02 89.77,93.87 v1(89.41,94.23)
  BOTTOM w0.102: 27.18,86.79 28.32,86.79 28.32,86.49 v1(28.7,86.11)
COM2_SET: length 99.7
  TOP w0.102: v1(32.26,77.8) 31.75,77.29 31.75,76.45 32.64,75.56 32.64,72.01 32.2,71.57 29.66,71.57 29.46,71.37 28.83,71.37 28.59,71.62 28.19,71.62 28.19,70.87 v1(28.45,70.61) ; v1(90.42,96.42) 89.97,96.88 R739.2
  L6-IN2 w0.102: v1(32.26,77.8) 34.47,77.8 34.86,77.41 35.64,77.41 36.62,76.43 43.42,76.43 43.98,76.99 54.07,76.99 55.53,75.53 56.16,75.53 57.3,74.4 57.3,73.54 58.3,72.54 67.71,72.54 69.12,73.94 86.68,73.94 87.79,75.04 89.86,75.04 91.33,76.51 91.33,79.34 91.77,79.78 91.77,85.14 91.19,85.72 91.19,87.63 90.49,88.32 90.49,96.35 v1(90.42,96.42)
  BOTTOM w0.102: 27.3,71.42 28.45,71.42 v1(28.45,70.61)
CSI_0_CLK_N:
  vias: v2(124.2,118.97) v3(124.2,118.97) v4(124.15,118.41) v5(112.71,99.62) v6(112.71,99.62)
CSI_0_CLK_P:
  vias: v2(124.71,118.97) v3(124.71,118.97) v4(124.76,118.41) v5(112.2,99.62) v6(112.2,99.62)
CSI_4_D0_N:
  vias: v2(116.9,118.18) v3(116.9,118.18) v4(116.85,117.62) v5(108.46,100.92) v6(108.46,100.92)
CSI_4_D0_P:
  vias: v2(117.41,118.18) v3(117.41,118.18) v4(117.46,117.62) v5(107.96,100.92) v6(107.96,100.92)
CSI_5_D1_N:
  vias: v2(103.22,118.84) v3(103.22,118.84) v4(103.17,118.11) v5(109.38,96.56) v6(109.38,96.56)
CSI_5_D1_P:
  vias: v2(103.73,118.84) v3(103.73,118.84) v4(103.78,118.11) v5(108.87,96.56) v6(108.87,96.56)
CSI_6_CLK_N:
  vias: v2(115.06,112.93) v3(115.06,112.93) v4(110.13,104.5) v5(110.19,104.06) v6(110.19,104.06)
CSI_6_CLK_P:
  vias: v2(115.56,112.93) v3(115.56,112.93) v4(110.74,104.5) v5(110.69,104.06) v6(110.69,104.06)
CTS1: length 30.4
  TOP w0.102: CN35.17 9.99,84.09 12.29,86.39 12.29,89.95 14.83,92.48 17.63,92.48 18.67,91.44 18.67,87.38 19.43,86.61 D50.2 20.21,86.76 21.59,88.14 v1(21.84,88.39)
  BOTTOM w0.102: v1(21.84,88.39) 21.84,90.42 22.63,91.21 23.68,91.21
CTS2: length 23.4
  TOP w0.102: v1(21.84,72.26) 21.84,71.75 20.83,70.74 D55.2 19.68,70.74 19.18,71.25 19.18,74.3 14.73,78.74 14.73,83.07 CN35.8
  BOTTOM w0.102: v1(21.84,72.26) 21.84,74.42 23.14,75.72 23.68,75.72
CVM_PRSNT: length 1.4
  BOTTOM w0.102: R455.2 90.35,81.84 89.9,81.39 Q38.1
D1-: length 20.5
  TOP w0.102: CN35.10 9.64,89.83 9.74,89.73 10.48,89.73 14.43,93.68 17.19,93.68 18.34,94.83 18.34,97.71 18.67,98.04 18.92,98.04 19.18,98.3 19.18,99.06 19.43,99.31 D54.2 20.21,98.32 v1(19.94,98.04)
  BOTTOM w0.102: R608.2 20.62,97.93 20.52,97.83 20.15,97.83 v1(19.94,98.04)
D2-: length 15.9
  TOP w0.102: v1(19.77,82.17) 20.21,82.61 D59.2 19.43,83.44 19.2,83.21 19.2,82.02 19.05,81.86 18.88,81.86 18.75,82 18.75,86.12 18.05,86.81 18.05,89.17 17.49,89.73 16.65,89.73 16.55,89.83 CN35.1
  BOTTOM w0.102: v1(19.77,82.17) 19.99,81.95 20.15,81.95 R663.2
DC_IN_EC: length 4.5
  BOTTOM w0.254: Q17.1 22.72,106.68 C125.1 22.91,107.12 R113.1 R112.2
DC_IN_EC_N: length 58.8
  TOP w0.102: v1(56.01,74.42) 56.01,74.19 55.36,73.54 U107.34
  L3-IN1 w0.089: v1(56.01,74.42) 55.12,75.31 55.12,75.69 53.53,77.28 47.75,77.28 44.32,80.71 44.32,87 44.07,87.25 35.05,87.25 34.54,87.76 34.54,98.3 32.92,99.92 27.27,99.92 v1(24.13,103.06)
  BOTTOM w0.102: Q17.3 v1(24.13,103.06) ; v1(56.01,74.42) 56.01,74.19 55.17,73.36 R560.2
DC_IN_GATE_CCG4: length 24.9
  TOP w0.102: v1(52.58,87.5) U98.2 52.58,84.45 52.32,84.2 R339.2 ; v1(55.37,74.42) 55,74.05 U107.35
  BOTTOM w0.102: U99.2 50.29,87.25 50.55,87.5 v1(52.58,87.5) 52.7,87.38 U97.2 52.7,86.23 52.96,85.98 53.34,85.98 54.1,85.22 55.24,85.22 56.49,83.97 56.49,82.38 57.23,81.64 57.23,80.85 56.54,80.16 56.54,79.02 54.86,77.34 54.86,74.93 v1(55.37,74.42)
DC_IN_GATE_CCG4_CTRL: length 63.7
  TOP w0.102: U100.1 v1(54.72,86.11) 54.72,86.38 53.64,87.46 U98.4 53.23,88.15 53.72,88.65 53.72,89.15 53.47,89.41 48.01,89.41 TP54.1 45.9,87.3 35.05,87.3 34.52,87.83 34.52,98.78 36.2,100.46 37.97,100.46 38.4,100.89 38.4,105.46 38.86,105.92 38.86,107.7 39.62,108.46 39.62,109.35 41.4,111.12 v1(41.53,111.12) ; U101.1 57.52,86.12 v1(57.02,86.61)
  BOTTOM w0.102: v1(54.72,86.11) 55.23,86.61 v1(57.02,86.61) ; Q67.1 46.24,115.41 R704.2 41.96,111.12 v1(41.53,111.12)
DC_IN_GATE_OE: length 3.2
  TOP w0.102: U102.4 50.43,86.85 51.05,86.23 51.69,86.23 51.93,85.99 U98.1
DCIN+_20V_EN: length 2.5
  TOP w0.102: U124.26 29.67,106.1 29.46,106.3 28.4,106.3 R700.2
DCIN+_VIN: length 4.2
  TOP w0.254: U124.27 29.27,105.6 29.1,105.42
  TOP w0.508: 29.1,105.42 C516.1 25.79,105.42 R701.1
DCIN+_VISNS: length 3.5
  TOP w0.203: U124.28 29.95,104.57 29.88,104.51
  TOP w0.508: R425.1 28.57,102.69 28.57,103.2 29.88,104.51
DI_GND: length 7.8
  TOP w0.508: 10.74,11.56 v1(11.43,11.56) ; v1(12.4,29.26) v1(13.03,29.26) ; 11.68,17.26 v1(10.68,17.26) ; 13.84,17.26 v1(12.83,17.27) ; 11.06,12.83 v1(12.06,12.83)
  BOTTOM w0.508: v1(12.4,29.26) 12.04,29.26 11.53,29.77 11.53,29.83 11.72,30.02 13.82,30.02
  vias: v1(6.1,22.99) v1(8.38,22.86) v1(9.53,22.23) v1(9.53,21.46) v1(11.05,14.22) v1(11.81,14.22) v1(13.97,13.97) v1(14.61,13.97) v1(16.89,5.33) v1(22.23,27.56) v1(22.31,25.95) v1(22.61,5.33) v1(22.73,16.51) v1(22.73,15.88) v1(22.73,15.24) v1(23.5,14.35) v1(24,27.56) v1(24.13,14.35) v1(24.77,14.35) v1(26.54,18.29) v1(26.54,17.65) v1(28.32,24) v1(28.7,19.3) v1(29.21,5.33) v1(31.88,24) v1(31.88,19.3) v1(33.02,5.33) v1(35.05,19.3) v1(35.81,24) v1(37.34,5.33) v1(38.23,19.3) v1(39.75,24) v1(41.27,22.48) v1(41.27,21.34) v1(42.16,8.13) v1(42.42,23.37)
DISCHARGE: length 106
  TOP w0.102: v1(66.93,103.76) 80.39,103.76 80.9,103.25 80.9,92.46 81.66,91.69 84.35,91.69 84.58,91.46 84.58,90.17 85.09,89.66 87.07,89.66 R116.1 88.01,89.99 88.01,87.6 90.93,84.68 90.93,83.95 92.33,82.55 92.33,81.28 91.84,80.79 Q9.1
  BOTTOM w0.102: v1(66.93,103.76) 66.05,104.63 D4.1 65.28,104.52 65.28,103.38 63.5,101.6 45.97,101.6 44.7,100.33 36.07,100.33 34.51,98.78 34.51,87.83 35.05,87.3 44.82,87.3 44.96,87.44 44.96,88.65 45.35,89.04 Q8.1
DISCHARGE_CAR: length 4.6
  TOP w0.102: R115.2 85.42,91.87 85.85,91.44 R114.1 R116.2 85.53,90.3 Q18.3
DO1_OUT:
  vias: v1(12.83,19.18) v1(12.83,18.54)
DO2_OUT:
  vias: v1(13.46,20.95) v1(14.1,20.95)
DO_GND1:
  vias: v1(12.32,45.85) v1(12.7,46.35)
DO_GND2:
  vias: v1(24.38,31.75)
DO_VDD:
  vias: v1(22.23,46.74)
DO_VIO:
  vias: v1(12.57,45.09) v1(12.57,44.45)
EFM8_FORCE_SHUTDOWN: length 11.9
  BOTTOM w0.102: U77.4 92.22,75.17 92.33,75.06 TP32.1 93.07,72.29 93.07,67.54 92.71,67.18 91.69,67.18 91.05,66.54 91.05,65.61
EFM8_P0_4: length 2.2
  BOTTOM w0.102: 92.16,64.51 92.16,64.52 TP48.1
EFM8_PSHOLD: length 3.8
  BOTTOM w0.102: R497.1 93.6,67.44 92.84,66.67 91.95,66.67 91.56,66.28 91.56,65.61
EFM8_RST_MON: length 5.6
  BOTTOM w0.102: TP36.1 92.41,68 R470.2 91.68,68.01 Q41.3 89.79,67.18 90.55,66.42 90.55,65.62 90.56,65.61
ENABLE1: length 2.3
  BOTTOM w0.102: 24.92,89.97 24.92,87.73 R617.1
ENABLE2: length 2.2
  BOTTOM w0.102: R671.1 25.02,73.03 24.92,73.12 24.92,74.48
GB_AVDDL:
  vias: v1(137.16,26.94) v1(139.83,26.92) v1(142.32,26.9) v1(145.29,27.94) v1(146.94,29.46) v1(147.57,29.46)
GB_VDDIO:
  vias: v1(126.87,21.46) v1(131.83,37.72) v1(131.83,37.08) v1(131.83,36.32) v1(132.97,34.04) v1(132.97,32.89) v1(132.97,31.62) v1(132.97,30.48) v1(132.97,29.34) v1(132.97,28.19) v1(136.02,32.48) v1(138.56,21.59) v1(139.57,39.62) v1(140.84,39.62) v1(141.6,39.62) v1(143.89,39.62) v1(144.91,39.62) v1(145.21,21.72) v1(145.8,33.02) v1(148.46,37.97) v1(149.48,35.18) v1(153.42,21.84)
GPIO_PMOS_ON: length 13.4
  TOP w0.102: v1(57.51,75.31) 57.66,75.46 TP57.1 57.63,76.02 R561.1 56.44,75.69 56.01,75.69 54.86,74.54 U107.36 ; v1(57.4,82.68) 57.64,82.92 U104.3
  BOTTOM w0.102: v1(57.4,82.68) 58.04,82.04 58.04,80.39 57.51,79.86 v1(57.51,75.31)
GPIO_PMOS_ON_CTRL: length 40.8
  TOP w0.102: v1(54.74,78.87) 54.94,78.87 55.7,79.63 R527.1 TP59.1 56.77,80.14 57.64,81.01 U104.4 ; 30.61,60.14 30.61,60.83 v1(30.73,60.96)
  BOTTOM w0.102: v1(30.73,60.96) 33.66,63.88 34.04,63.88 35.5,65.34 35.5,68.19 37.02,69.72 38.95,69.72 41.6,72.36 42.84,72.36 43.46,72.98 43.46,75.59 43.69,75.82 44.77,75.82 48.35,79.4 51.22,79.4 52.26,78.36 54.23,78.36 v1(54.74,78.87)
HDMI_DP0_TX2_N: length 3.1
  BOTTOM w0.089: v6(58.13,56.77) 58.04,56.67 58.04,54.36 58.47,53.92
  vias: v5(104.36,94.79) v6(104.36,94.79)
HDMI_DP0_TX2_P: length 3
  BOTTOM w0.089: 57.33,53.92 57.72,54.32 57.72,56.67 v6(57.63,56.77)
  vias: v5(104.87,94.79) v6(104.87,94.79)
HDMI_GND: length 140.6
  TOP w0.508: 0.98,37.92 0.98,38.95 v1(1.27,39.24) ; v1(1.27,41.53) 0.98,41.24 0.98,40.44 ; v1(1.27,35.56) 0.98,35.27 0.98,34.22 ; 0.98,44.14 0.98,45.18 v1(1.27,45.47)
  L2-GND1 w0.508: CN35.H1 14.8,100 ; CN35.H1 14.8,95.93 ; CN35.H1 12.77,97.97 ; CN35.H1 16.83,97.97 ; 6.8,95.93 CN35.H3 ; CN35.H3 4.77,97.97 ; CN35.H3 8.83,97.97 ; CN35.H3 6.8,100 ; 2.86,96.84 2.61,97.08 ; CN35.H4 8.83,72.98 ; CN35.H4 6.8,70.94 ; CN35.H4 4.77,72.98 ; CN35.H4 6.8,75.01 ; 12.77,72.98 CN35.H2 ; CN35.H2 14.8,70.94 ; CN35.H2 16.83,72.98 ; CN35.H2 14.8,75.01 ; 2.67,88.01 2.6,88.08
  L4-VCC1 w0.508: CN35.H2 16.83,72.98 ; CN35.H2 12.77,72.98 ; CN35.H2 14.8,70.94 ; CN35.H2 14.8,75.01 ; 6.8,95.93 CN35.H3 ; CN35.H3 4.77,97.97 ; CN35.H3 8.83,97.97 ; CN35.H3 6.8,100 ; 159.51,10.03 159.04,10.5 159.04,11.41 ; 4.77,72.98 CN35.H4 ; CN35.H4 6.8,70.94 ; CN35.H4 6.8,75.01 ; CN35.H4 8.83,72.98 ; 14.8,95.93 CN35.H1 ; CN35.H1 16.83,97.97 ; CN35.H1 14.8,100 ; CN35.H1 12.77,97.97
  L5-VCC2 w0.508: 12.77,97.97 CN35.H1 ; CN35.H1 14.8,100 ; CN35.H1 16.83,97.97 ; CN35.H1 14.8,95.93 ; CN35.H2 14.8,75.01 ; CN35.H2 14.8,70.94 ; CN35.H2 12.77,72.98 ; CN35.H2 16.83,72.98 ; 4.77,72.98 CN35.H4 ; CN35.H4 8.83,72.98 ; CN35.H4 6.8,75.01 ; CN35.H4 6.8,70.94 ; CN35.H3 6.8,100 ; CN35.H3 8.83,97.97 ; CN35.H3 6.8,95.93 ; CN35.H3 4.77,97.97 ; 159.04,11.41 159.04,10.5 159.51,10.03
  L7-GND2 w0.508: 6.8,70.94 CN35.H4 ; CN35.H4 6.8,75.01 ; CN35.H4 8.83,72.98 ; CN35.H4 4.77,72.98 ; 159.04,11.41 159.04,10.5 159.38,10.16 ; CN35.H2 14.8,75.01 ; CN35.H2 12.77,72.98 ; CN35.H2 14.8,70.94 ; CN35.H2 16.83,72.98 ; 14.8,95.93 CN35.H1 ; CN35.H1 14.8,100 ; CN35.H1 12.77,97.97 ; CN35.H1 16.83,97.97 ; CN35.H3 6.8,100 ; CN35.H3 4.77,97.97 ; CN35.H3 8.83,97.97 ; CN35.H3 6.8,95.93
  vias: v1(1.27,97.28) v1(1.27,94.23) v1(1.27,91.06) v1(1.27,88.27) v1(1.27,85.09) v1(1.27,82.42) v1(1.27,79.25) v1(1.27,77.22) v1(1.27,74.8) v1(1.27,71.63) v1(1.27,70.36) v1(1.27,66.67) v1(1.27,63.5) v1(1.27,59.44) v1(1.27,55.37) v1(1.27,49.91) v1(1.78,100.71) v1(2.54,25.4) v1(2.54,20.32) v1(2.54,15.24) v1(2.54,10.16) v1(3.94,97.28) v1(3.94,94.23) v1(3.94,91.06) v1(3.94,88.27) v1(3.94,85.09) v1(3.94,82.42) v1(3.94,79.25) v1(3.94,77.22) v1(3.94,74.8) v1(3.94,71.63) v1(4.83,100.71) v1(9.4,100.71) v1(9.4,96.39) v1(9.4,74.8) v1(9.4,70.87) v1(10.16,1.52) v1(12.19,74.8) v1(12.19,70.87) v1(12.32,100.71) v1(12.32,96.39) v1(15.24,1.52) v1(16.26,100.71) v1(20.32,1.52) v1(25.4,1.52) v1(30.48,1.52) v1(35.56,1.52) v1(40.64,1.52) v1(46.35,8.76) v1(46.35,4.95) v1(46.35,1.4) v1(50.93,4.83) v1(50.93,1.4) v1(54.99,1.4) v1(55.12,4.83) v1(55.88,12.83) v1(55.88,8.76) v1(58.29,17.4) v1(58.29,12.95) v1(58.42,8.76) v1(58.67,4.83) v1(58.67,1.4) v1(59.94,4.83) v1(59.94,1.4) v1(59.99,8.55) v1(66.34,4.74) v1(66.29,1.4) v1(66.42,8.13) v1(72.26,8.13) v1(72.3,4.74) v1(72.26,1.4) v1(74.46,11.6) v1(75.61,10.97) v1(77,11.6) v1(77,4.74) v1(76.96,1.4) v1(78.38,9.32) v1(78.51,4.74) v1(78.51,1.44) v1(84.48,7.79) v1(84.48,4.74) v1(84.48,1.44) v1(90.07,7.79) v1(90.19,4.74) v1(90.19,1.44) v1(92.61,11.73) v1(94.87,15.88) v1(95.53,11.6) v1(96.01,8.13) v1(96.01,4.83) v1(96.01,1.52) v1(96.27,14.48) v1(97.03,14.48) v1(97.79,14.48) v1(98.81,11.68) v1(99.06,14.99) v1(100.08,14.99) v1(100.84,16) v1(100.84,8.13) v1(100.84,4.83) v1(100.84,1.52) v1(101.6,12.7) v1(102.36,16) v1(119.38,12.7) v1(119.89,7.62) v1(119.89,5.08) v1(119.89,2.54) v1(120.14,19.3) v1(120.14,18.54) v1(120.14,15.24) v1(121.28,19.3) v1(121.28,18.54) v1(121.92,12.7) v1(121.92,10.16) v1(121.92,7.62) v1(121.92,5.08) v1(121.92,2.54) v1(122.43,19.3) v1(122.43,18.54) v1(122.43,15.24) v1(126.87,1.4) v1(132.21,1.4) v1(137.54,1.4) v1(139.7,15.24) v1(139.7,12.7) v1(139.83,18.16) v1(139.83,17.4) v1(140.72,18.16) v1(140.72,17.4) v1(141.22,9.91) v1(141.22,6.86) v1(141.22,4.06) v1(142.18,19.3) v1(142.18,18.54) v1(142.24,15.24) v1(142.24,12.7) v1(142.24,1.52) v1(143,19.3) v1(143,18.54) v1(147.32,1.52) v1(152.4,1.52) v1(155.45,21.59) v1(156.21,21.59) v1(156.97,21.59) v1(157.48,19.81) v1(157.48,1.52) v1(159.51,17.78) v1(159.51,14.99) v1(159.77,12.95) v1(160.02,9.4) v1(160.02,7.11) v1(160.02,4.32)
I2C_GP2_CLK_3V3: length 1.8
  TOP w0.102: U107.17 47.36,73.54 46.89,74.02 v1(46.89,74.04)
I2C_GP2_DAT_3V3: length 0.9
  TOP w0.102: U107.16 v1(47.53,74.05)
I2C_INT_CCG4: length 22.1
  TOP w0.102: v1(41.63,73.41) 41.63,73.05 43.83,70.85 Q52.2 43.83,70.34 44.15,70.03 R551.2
  BOTTOM w0.102: v1(41.63,73.41) 41.63,73.51 42.82,74.7 42.82,76.33 44.28,77.79 45.84,77.79 47.62,79.57 47.62,83.12 46.63,84.11 v1(46.63,86.74)
I2C_INT_CCG4_3V3: length 6.4
  TOP w0.102: U107.15 46.68,74.54 46.18,74.04 R550.2 46.18,73.43 45.77,73.03 44.75,73.03 44.43,72.7 Q52.3
IRQ_PD_N: length 2.6
  TOP w0.102: U107.26 51.68,69.52 R782.2
ISO1_5V:
  vias: v1(8.64,13.59) v1(9.14,11.43)
JTAG_TRST_N: length 1.1
  TOP w0.102: R480.1 R481.2
M2B_3V3:
  vias: v1(158.43,72.33) v1(158.5,80.52) v1(158.5,79.88) v1(158.5,79.24) v1(158.5,78.59) v1(158.5,77.91) v1(158.88,59.75) v1(158.88,59.12) v1(159.13,79.88) v1(159.13,79.24) v1(159.13,78.59) v1(159.13,77.93) v1(159.13,77.28) v1(159.13,67.56) v1(159.32,58.23) v1(159.32,57.47) v1(159.89,58.55) v1(159.89,57.78) v1(164.97,72.64)
M2E_3V3:
  vias: v1(146.69,78.11) v1(146.69,77.47) v1(147.07,59.94) v1(147.07,59.31) v1(147.32,78.11) v1(147.32,77.47)
M2M_3V3:
  vias: v1(161.54,103) v1(161.54,102.36) v1(161.54,101.73) v1(161.54,88.58) v1(161.54,87.95) v1(161.8,105.54) v1(162.18,101.73) v1(162.18,88.6) v1(162.18,87.96) v1(162.43,105.54)
M_USB_GND:
  vias: v1(182.88,138.18) v1(184.53,116.46) v1(184.53,115.82) v1(184.78,103.89) v1(185.17,116.46) v1(185.17,115.82) v1(187.2,89.41) v1(187.2,88.65) v1(187.2,87.88) v1(187.96,138.18) v1(187.96,132.08) v1(187.96,127.76) v1(187.96,123.44) v1(187.96,119.51) v1(187.96,115.32) v1(187.96,103.38) v1(188.07,100.84) v1(188.07,90.19) v1(188.21,111.89) v1(188.21,108.58) v1(188.21,105.54)
MGBE_0V7:
  vias: v1(105.66,36.32) v1(105.66,35.69) v1(106.3,36.32) v1(106.3,35.69) v1(106.93,36.32) v1(106.93,35.69) v7(109.44,35.47) v7(110.24,36.27) v7(110.24,33.07) v7(111,33.91) v7(111.08,34.72)
MGBE_V10_SRDS:
  vias: v7(109.44,37.07)
MGBE_V20_SRDS:
  vias: v7(111.84,37.07)
MGBE_VA10:
  vias: v7(110.24,32.27)
MGBE_VA20:
  vias: v7(110.29,31.42)
MGBE_VDDIO:
  vias: v1(99.44,30.86) v1(99.44,29.08) v1(99.57,26.92) v1(102.11,26.92) v1(113.11,40.58) v1(114.55,40.51) v1(119.89,40.51) v1(119.86,39.37) v1(119.89,38.23) v1(122.94,38.61) v1(123.44,37.59) v1(123.44,36.96) v1(124.08,37.59) v1(124.08,36.96) v1(124.71,37.59) v1(124.71,36.96) v1(125.86,28.19) v1(125.86,27.56) v1(125.98,32.13)
MIC2128_3V3_DH: length 6.2
  TOP w0.762: Q6.4 65.28,95.23 R35.1
MIC2128_3V3_DL: length 4.5
  TOP w0.762: R40.1 C61.1 Q7.4
MIC2128_3V3_SW: length 11.4
  TOP w0.508: Q6.3 66.29,97.28 67.06,96.52 67.06,95 66.67,94.61 66.67,91.57 67.69,90.55 R36.1 R39.1 68.83,90.32 v1(68.34,90.82)
  BOTTOM w0.508: C47.2 v1(68.34,90.82)
MOD_SHUTDOWN_N_3V3: length 5.5
  BOTTOM w0.102: 96.23,80.02 95.63,80.02 95.59,80.06 95.25,80.06 95.25,79.12 TP34.1 95.12,78.41 94.74,78.03 94.74,76.94 94.28,76.47 U77.1
MODULE_POWER_ON: length 6.4
  BOTTOM w0.102: 84.88,63.26 84.57,63.26 84.07,63.75 84.07,64.19 84.33,64.44 R503.1 84.66,64.44 85.34,63.75 87.54,63.75 v1(88.3,64.52)
OCP_USBC1_N: length 34.9
  TOP w0.102: U107.5 51.68,77.97 53.21,79.5 53.21,79.68 R557.2 53.47,79.68 v1(53.47,78.87) ; 32.77,64.57 v1(33.91,64.57)
  BOTTOM w0.102: v1(53.47,78.87) 52.33,78.87 51.39,79.81 48.18,79.81 45.91,77.53 44.35,77.53 43.05,76.23 43.05,73.15 42.67,72.77 41.43,72.77 38.82,70.17 36.89,70.17 35.09,68.36 35.09,65.75 v1(33.91,64.57)
PCIE4_CLK_N:
  vias: v2(163.77,93.28) v3(163.77,93.28) v4(132.81,96.08) v5(132.76,96.52) v6(132.76,96.52)
PCIE4_CLK_P:
  vias: v2(163.77,92.77) v3(163.77,92.77) v4(132.2,96.08) v5(132.25,96.52) v6(132.25,96.52)
PCIE_3V3:
  vias: v1(163.07,130.05) v1(163.07,129.41) v1(163.45,137.41) v1(163.45,136.78) v1(163.45,136.14) v1(163.45,135.51) v1(163.7,130.05) v1(163.7,129.41) v1(164.08,137.41) v1(164.08,135.56) v1(164.34,130.05) v1(164.34,129.41) v1(177.29,125.73) v1(179.32,126.49) v1(179.32,125.35) v1(179.32,124.71) v1(179.96,127.13) v1(179.96,126.49) v1(179.96,125.35) v1(179.96,124.71) v1(180.59,127.13) v1(180.59,126.49) v1(180.59,125.35) v1(180.59,124.71) v1(181.23,127.13) v1(181.23,126.49) v1(181.23,125.35) v1(181.23,124.71)
PCIE_12V_EN_N: length 42.6
  TOP w0.102: Q14.1 70.37,110.9 69.85,110.39 v1(69.85,109.98) 69.85,109.3 R105.2
  BOTTOM w0.102: v1(91.57,88.39) 81.29,88.39 80.9,88.79 80.9,104.65 78.87,106.68 72.52,106.68 69.85,109.35 v1(69.85,109.98)
PD_FW_PWR: length 5.6
  TOP w0.508: R850.1 R851.1 63.55,71.53 65.81,73.79 CN19.1
PD_SWD_CLK: length 14
  TOP w0.102: U107.2 53.19,77.88 53.29,77.98 55.06,77.98 55.74,78.66 59.39,78.66 CN19.2
PD_SWD_IO: length 11.7
  TOP w0.102: U107.1 53.68,77.5 53.79,77.6 55.11,77.6 55.87,78.36 59.26,78.36 61.72,75.9 CN19.3
PEX_TX14_N: length 3
  TOP w0.102: 92.18,133.77 92.18,134.77 92.58,135.16 92.58,135.97 C244.2
PS_1V8_BODE: length 2.3
  TOP w0.254: R56.1 C69.1 R55.2
PS_1V8_BOOT: length 3.4
  TOP w0.254: U3.7 81.53,82.8 81.79,83.06
  TOP w0.508: 81.79,83.06 82.04,83.31 82.04,84.71 82.5,85.17 C67.1
PS_1V8_EN: length 5.4
  TOP w0.102: U3.11 79.64,83.68 78.17,85.15 78.17,86.6 R52.2 R53.2
PS_1V8_FB: length 2.2
  TOP w0.254: U3.10 80.14,83.99 R54.1
PS_1V8_FB_R: length 3.4
  TOP w0.254: R57.1 R54.2 78.79,86.26 C69.2 R56.2
PS_1V8_PG: length 1
  BOTTOM w0.102: R72.1 R73.2
